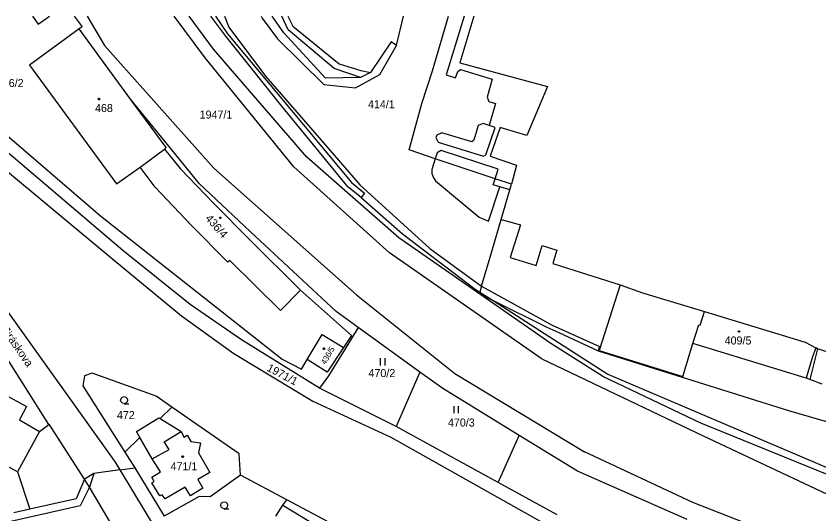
# Model space of a CAD drawing. Extents: x -621797 to -620972, y -1175539 to -1174697.
# Drawn here: x -621483.9 to -621313.4, y -1174804.6 to -1174699 of the extents above; entities that cross this region are included whole.
import ezdxf

# ---------------------------------------------------------------- set-up
doc = ezdxf.new("R2010")
doc.units = 0
for name, color, linetype in [('INZ mimo EON - nadz', 7, 'Continuous'), ('Rozvod plynu EON', 7, 'Continuous'), ('SDEL EON', 7, 'Continuous'), ('SDEL EON - popis', 7, 'Continuous'), ('Silnoproud EON', 7, 'Continuous'), ('Silnoproud EON - popis', 7, 'Continuous')]:
    doc.layers.add(name, color=color, linetype=linetype)

msp = doc.modelspace()

# ---------------------------------------------------------------- linework, layer by layer
at = {"layer": 'Rozvod plynu EON'}
for points in [[(-621466.21, -1174716.4), (-621466.12, -1174716.55), (-621466.21, -1174716.7), (-621466.39, -1174716.7), (-621466.48, -1174716.55), (-621466.39, -1174716.4)], [(-621440.42, -1174741.62), (-621440.33, -1174741.77), (-621440.42, -1174741.92), (-621440.6, -1174741.92), (-621440.69, -1174741.77), (-621440.6, -1174741.62)], [(-621330.31, -1174765.75), (-621330.22, -1174765.9), (-621330.31, -1174766.05), (-621330.49, -1174766.05), (-621330.58, -1174765.9), (-621330.49, -1174765.75)], [(-621418.44, -1174769.38), (-621418.35, -1174769.53), (-621418.44, -1174769.68), (-621418.62, -1174769.68), (-621418.71, -1174769.53), (-621418.62, -1174769.38)], [(-621448.44, -1174792.3), (-621448.35, -1174792.45), (-621448.44, -1174792.6), (-621448.62, -1174792.6), (-621448.71, -1174792.45), (-621448.62, -1174792.3)]]:
    msp.add_lwpolyline(points, close=True, dxfattribs=at)
at = {"layer": 'SDEL EON'}
for p, q in [((-621406.55, -1174771.58), (-621406.55, -1174773.08)), ((-621405.55, -1174773.08), (-621405.55, -1174771.58)), ((-621390.95, -1174781.71), (-621390.95, -1174783.21)), ((-621389.95, -1174783.21), (-621389.95, -1174781.71))]:
    msp.add_line(p, q, dxfattribs=at)
for points in [[(-621460.93, -1174781.19), (-621461.31, -1174781.09), (-621461.58, -1174780.82), (-621461.68, -1174780.45), (-621461.58, -1174780.08), (-621461.31, -1174779.81), (-621460.94, -1174779.71), (-621460.57, -1174779.81), (-621460.3, -1174780.08), (-621460.2, -1174780.46), (-621460.3, -1174780.84), (-621460.57, -1174781.11), (-621460.95, -1174781.21), (-621459.95, -1174781.21)], [(-621439.69, -1174803.5), (-621440.07, -1174803.4), (-621440.34, -1174803.13), (-621440.44, -1174802.76), (-621440.34, -1174802.39), (-621440.07, -1174802.12), (-621439.7, -1174802.02), (-621439.33, -1174802.12), (-621439.06, -1174802.39), (-621438.96, -1174802.77), (-621439.06, -1174803.15), (-621439.33, -1174803.42), (-621439.71, -1174803.52), (-621438.71, -1174803.52)]]:
    msp.add_lwpolyline(points, dxfattribs=at)
at = {"layer": 'SDEL EON - popis'}
for p, q in [((-621468.802, -1174698.96), (-621465.12, -1174705.2)), ((-621443.71, -1174707.79), (-621450.351, -1174698.96)), ((-621442.35, -1174699.28), (-621442.563, -1174698.96)), ((-621439.36, -1174703.2), (-621442.35, -1174699.28)), ((-621441.542, -1174698.96), (-621439, -1174702.7)), ((-621431.858, -1174698.96), (-621431.64, -1174699.42)), ((-621431.64, -1174699.42), (-621428.41, -1174703.82)), ((-621427.05, -1174702.51), (-621429.478, -1174698.96)), ((-621426.13, -1174701.85), (-621427.487, -1174698.96)), ((-621426.21, -1174698.96), (-621425.12, -1174701.13)), ((-621403.08, -1174705.22), (-621401.632, -1174698.96)), ((-621388.71, -1174698.96), (-621392.56, -1174711.42)), ((-621386.669, -1174698.96), (-621389.68, -1174708.86)), ((-621425.12, -1174701.13), (-621415.27, -1174709.1)), ((-621427.46, -1174718.1), (-621439.36, -1174703.2)), ((-621439, -1174702.7), (-621426.74, -1174717.4)), ((-621418.2, -1174712.15), (-621427.05, -1174702.51)), ((-621416.32, -1174710.11), (-621426.13, -1174701.85)), ((-621428.41, -1174703.82), (-621418.55, -1174713.48)), ((-621404.23, -1174704.42), (-621408.6, -1174710.95)), ((-621403.08, -1174705.22), (-621404.23, -1174704.42)), ((-621465.12, -1174705.2), (-621441.9, -1174731.26)), ((-621406.68, -1174711.35), (-621403.08, -1174705.22)), ((-621424.92, -1174730.95), (-621443.71, -1174707.79)), ((-621410.72, -1174712.01), (-621416.32, -1174710.11)), ((-621415.27, -1174709.1), (-621410.66, -1174710.51)), ((-621389.68, -1174708.86), (-621371.05, -1174713.9)), ((-621411.85, -1174714.16), (-621406.68, -1174711.35)), ((-621408.6, -1174710.95), (-621410.72, -1174712.01)), ((-621410.66, -1174710.51), (-621408.6, -1174710.95)), ((-621392.56, -1174711.42), (-621390.58, -1174712.1)), ((-621390.58, -1174712.1), (-621390.09, -1174710.72)), ((-621390.09, -1174710.72), (-621389.51, -1174710.28)), ((-621389.51, -1174710.28), (-621382.83, -1174712.37)), ((-621499.28, -1174712.78), (-621465.93, -1174741.34)), ((-621418.55, -1174713.48), (-621411.85, -1174714.16)), ((-621410.72, -1174712.01), (-621418.2, -1174712.15)), ((-621382.83, -1174712.37), (-621383.89, -1174716.19)), ((-621371.05, -1174713.9), (-621375.46, -1174724.27)), ((-621383.89, -1174716.19), (-621383.52, -1174717.06)), ((-621413.37, -1174735.29), (-621427.46, -1174718.1)), ((-621426.74, -1174717.4), (-621412.65, -1174734.3)), ((-621383.52, -1174717.06), (-621382.09, -1174717.53)), ((-621382.09, -1174717.53), (-621383.46, -1174722.16)), ((-621384.73, -1174721.75), (-621385.77, -1174722.2)), ((-621383.46, -1174722.16), (-621384.73, -1174721.75)), ((-621393.51, -1174723.72), (-621394.56, -1174724.26)), ((-621387.12, -1174725.62), (-621393.51, -1174723.72)), ((-621385.77, -1174722.2), (-621386.72, -1174725.27)), ((-621384.11, -1174728.42), (-621382.16, -1174722.58)), ((-621382.16, -1174722.58), (-621383.46, -1174722.16)), ((-621381.11, -1174722.58), (-621383.19, -1174728.68)), ((-621375.46, -1174724.27), (-621381.11, -1174722.58)), ((-621394.56, -1174724.26), (-621394.76, -1174724.75)), ((-621394.76, -1174724.75), (-621394.24, -1174725.69)), ((-621386.72, -1174725.27), (-621387.12, -1174725.62)), ((-621394.24, -1174725.69), (-621384.65, -1174728.68)), ((-621394.49, -1174727.98), (-621394.9, -1174729.24)), ((-621393.61, -1174727.47), (-621394.49, -1174727.98)), ((-621381.5, -1174731.43), (-621393.61, -1174727.47)), ((-621384.65, -1174728.68), (-621384.11, -1174728.42)), ((-621383.19, -1174728.68), (-621377.63, -1174730.58)), ((-621394.9, -1174729.24), (-621395.63, -1174731.5)), ((-621441.9, -1174731.26), (-621411.59, -1174758.13)), ((-621404.62, -1174749.2), (-621424.92, -1174730.95)), ((-621395.63, -1174731.5), (-621395.61, -1174732.39)), ((-621382.17, -1174733.49), (-621381.5, -1174731.43)), ((-621377.63, -1174730.58), (-621378.72, -1174734.65)), ((-621395.61, -1174732.39), (-621395.29, -1174733.27)), ((-621395.29, -1174733.27), (-621394.85, -1174733.94)), ((-621394.85, -1174733.94), (-621385.58, -1174741.65)), ((-621382.6, -1174734.79), (-621382.17, -1174733.49)), ((-621410.61, -1174737.48), (-621413.37, -1174735.29)), ((-621412.65, -1174734.3), (-621409.93, -1174736.57)), ((-621383.56, -1174742.46), (-621381.16, -1174735.21)), ((-621381.16, -1174735.21), (-621382.6, -1174734.79)), ((-621379.06, -1174735.82), (-621381.16, -1174735.21)), ((-621409.93, -1174736.57), (-621410.61, -1174737.48)), ((-621410.61, -1174737.48), (-621401.84, -1174745.2)), ((-621465.93, -1174741.34), (-621427.37, -1174771.79)), ((-621385.58, -1174741.65), (-621383.56, -1174742.46)), ((-621380.91, -1174742.13), (-621376.81, -1174743.24)), ((-621376.81, -1174743.24), (-621378.96, -1174750.2)), ((-621401.84, -1174745.2), (-621386.41, -1174756.88)), ((-621372.39, -1174771.62), (-621404.62, -1174749.2)), ((-621373.49, -1174751.92), (-621372.17, -1174747.66)), ((-621372.17, -1174747.66), (-621369.05, -1174748.62)), ((-621369.05, -1174748.62), (-621369.93, -1174751.49)), ((-621378.96, -1174750.2), (-621373.49, -1174751.92)), ((-621369.93, -1174751.49), (-621355.64, -1174755.99)), ((-621355.64, -1174755.99), (-621360.06, -1174769.93)), ((-621355.64, -1174755.99), (-621350.85, -1174757.71)), ((-621423.47, -1174757.15), (-621412.66, -1174766.73)), ((-621386.41, -1174756.88), (-621385.42, -1174757.52)), ((-621385.42, -1174757.52), (-621382.57, -1174759.34)), ((-621385.06, -1174756.29), (-621370.06, -1174764.58)), ((-621350.85, -1174757.71), (-621337.7, -1174761.64)), ((-621411.59, -1174758.13), (-621390.7, -1174774.81)), ((-621382.57, -1174759.34), (-621369.69, -1174767.58)), ((-621370.06, -1174764.58), (-621360.01, -1174769.05)), ((-621412.66, -1174766.73), (-621414.35, -1174769.32)), ((-621369.69, -1174767.58), (-621358.21, -1174774.93)), ((-621360.01, -1174769.05), (-621360.28, -1174770.03)), ((-621342.32, -1174775.41), (-621340.2, -1174768.47)), ((-621313.73, -1174769.59), (-621315.34, -1174776.05)), ((-621313.73, -1174769.59), (-621314.1, -1174769.35)), ((-621249.98, -1174789.27), (-621313.73, -1174769.59)), ((-621360.06, -1174769.93), (-621342.32, -1174775.41)), ((-621427.37, -1174771.79), (-621423.25, -1174773.91)), ((-621423.25, -1174773.91), (-621422.11, -1174771.81)), ((-621372.39, -1174771.62), (-621338, -1174788.06)), ((-621390.7, -1174774.81), (-621363.22, -1174791.43)), ((-621358.21, -1174774.93), (-621305.79, -1174797.28)), ((-621315.34, -1174776.05), (-621316.14, -1174775.82)), ((-621312.71, -1174777.06), (-621315.34, -1174776.05)), ((-621453.31, -1174784.34), (-621448.83, -1174787.11)), ((-621478.9, -1174787.1), (-621483.6, -1174795.66)), ((-621454.97, -1174792.88), (-621457.58, -1174788.41)), ((-621452.42, -1174789.29), (-621448.83, -1174787.11)), ((-621448.83, -1174787.11), (-621448.25, -1174788.29)), ((-621448.25, -1174788.29), (-621447.54, -1174787.88)), ((-621447.54, -1174787.88), (-621446.8, -1174789.23)), ((-621338, -1174788.06), (-621307.33, -1174802.47)), ((-621451.38, -1174790.93), (-621452.42, -1174789.29)), ((-621446.8, -1174789.23), (-621444.7, -1174789.5)), ((-621444.7, -1174789.5), (-621445.16, -1174791.62)), ((-621454.97, -1174792.88), (-621451.38, -1174790.93)), ((-621445.16, -1174791.62), (-621442.74, -1174795.78)), ((-621340.16, -1174802.18), (-621363.22, -1174791.43)), ((-621483.6, -1174795.66), (-621487.41, -1174793.6)), ((-621453.23, -1174795.64), (-621454.97, -1174792.88)), ((-621461.85, -1174795.25), (-621402.58, -1174893.11)), ((-621483.6, -1174795.66), (-621480.94, -1174803.61)), ((-621467.38, -1174796.02), (-621468.3, -1174798.95)), ((-621455.09, -1174796.8), (-621453.23, -1174795.64)), ((-621454.55, -1174797.71), (-621455.09, -1174796.8)), ((-621442.74, -1174795.78), (-621445.31, -1174797.31)), ((-621455.04, -1174798.01), (-621454.55, -1174797.71)), ((-621453.37, -1174800.79), (-621455.04, -1174798.01)), ((-621445.31, -1174797.31), (-621444.22, -1174799.14)), ((-621468.3, -1174798.95), (-621470.29, -1174802.9)), ((-621448, -1174798.9), (-621452.25, -1174801.41)), ((-621446.85, -1174800.74), (-621448, -1174798.9)), ((-621444.22, -1174799.14), (-621446.85, -1174800.74)), ((-621452.87, -1174800.52), (-621453.37, -1174800.79)), ((-621452.25, -1174801.41), (-621452.87, -1174800.52)), ((-621470.29, -1174802.9), (-621493.86, -1174808.23)), ((-621427.21, -1174802.78), (-621419.69, -1174807.36)), ((-621323.55, -1174808.67), (-621340.16, -1174802.18))]:
    msp.add_line(p, q, dxfattribs=at)
at = {"layer": 'Silnoproud EON'}
for p, q in [((-621480.414, -1174698.96), (-621479.19, -1174700.68)), ((-621479.19, -1174700.68), (-621476.788, -1174698.96)), ((-621471.523, -1174698.96), (-621469.88, -1174701.25)), ((-621441.97, -1174705.95), (-621447.1, -1174698.96)), ((-621439.637, -1174698.96), (-621438.72, -1174701.33)), ((-621395.48, -1174710.6), (-621392.081, -1174698.96)), ((-621469.88, -1174701.25), (-621470.51, -1174701.7)), ((-621438.72, -1174701.33), (-621430.9, -1174711.72)), ((-621470.51, -1174701.7), (-621481.06, -1174709.36)), ((-621459.57, -1174716.57), (-621470.51, -1174701.7)), ((-621422.13, -1174728.91), (-621441.97, -1174705.95)), ((-621513.67, -1174708.79), (-621462.91, -1174750.9)), ((-621481.06, -1174709.36), (-621462.56, -1174734.54)), ((-621430.9, -1174711.72), (-621419.52, -1174724.79)), ((-621397.72, -1174717.48), (-621395.48, -1174710.6)), ((-621461.21, -1174748.72), (-621500.92, -1174714.95)), ((-621452.64, -1174725.1), (-621459.57, -1174716.57)), ((-621451.99, -1174726.87), (-621459.57, -1174716.57)), ((-621400.44, -1174727.38), (-621397.72, -1174717.48)), ((-621444.97, -1174734.55), (-621452.64, -1174725.1)), ((-621419.52, -1174724.79), (-621410.9, -1174734.74)), ((-621452.39, -1174727.17), (-621451.99, -1174726.87)), ((-621457.57, -1174731), (-621452.39, -1174727.17)), ((-621452.39, -1174727.17), (-621449.03, -1174731.31)), ((-621394.9, -1174729.24), (-621400.44, -1174727.38)), ((-621402.61, -1174746.04), (-621422.13, -1174728.91)), ((-621382.17, -1174733.49), (-621394.9, -1174729.24)), ((-621462.56, -1174734.54), (-621457.57, -1174731)), ((-621454.34, -1174735.3), (-621457.57, -1174731)), ((-621449.03, -1174731.31), (-621441.96, -1174738.68)), ((-621378.72, -1174734.65), (-621382.17, -1174733.49)), ((-621446.67, -1174743.39), (-621454.34, -1174735.3)), ((-621434.16, -1174744.65), (-621444.97, -1174734.55)), ((-621410.9, -1174734.74), (-621396, -1174748.28)), ((-621379.06, -1174735.82), (-621378.72, -1174734.65)), ((-621380.91, -1174742.13), (-621379.06, -1174735.82)), ((-621441.96, -1174738.68), (-621434.16, -1174746.51)), ((-621383.24, -1174750.1), (-621380.91, -1174742.13)), ((-621438.9, -1174751.16), (-621446.67, -1174743.39)), ((-621415.93, -1174761.66), (-621434.16, -1174744.65)), ((-621434.16, -1174746.51), (-621423.47, -1174757.15)), ((-621370.32, -1174768.47), (-621402.61, -1174746.04)), ((-621446.92, -1174760.16), (-621461.21, -1174748.72)), ((-621396, -1174748.28), (-621385.06, -1174756.29)), ((-621494.1, -1174749.94), (-621462.84, -1174793.62)), ((-621462.91, -1174750.9), (-621448.78, -1174762.54)), ((-621438.5, -1174750.8), (-621438.9, -1174751.16)), ((-621427.77, -1174761.47), (-621438.5, -1174750.8)), ((-621385.06, -1174756.29), (-621383.24, -1174750.1)), ((-621476.96, -1174785.62), (-621498.01, -1174752.31)), ((-621423.47, -1174757.15), (-621427.77, -1174761.47)), ((-621385.42, -1174757.52), (-621385.52, -1174757.88)), ((-621385.06, -1174756.29), (-621385.42, -1174757.52)), ((-621385.52, -1174757.88), (-621382.57, -1174759.34)), ((-621382.57, -1174759.34), (-621371.17, -1174764.97)), ((-621436.01, -1174767.68), (-621446.92, -1174760.16)), ((-621448.78, -1174762.54), (-621437.66, -1174770.55)), ((-621411.24, -1174765.05), (-621415.93, -1174761.66)), ((-621338.66, -1174764.58), (-621337.7, -1174761.64)), ((-621337.7, -1174761.64), (-621316.34, -1174768.15)), ((-621340.2, -1174768.47), (-621338.9, -1174764.51)), ((-621338.9, -1174764.51), (-621338.66, -1174764.58)), ((-621411.24, -1174765.05), (-621412.67, -1174767.36)), ((-621398.13, -1174774.52), (-621411.24, -1174765.05)), ((-621371.17, -1174764.97), (-621368.65, -1174766.14)), ((-621368.65, -1174766.14), (-621360.28, -1174770.03)), ((-621419.48, -1174777.93), (-621436.01, -1174767.68)), ((-621422.11, -1174771.81), (-621418.91, -1174766.5)), ((-621418.91, -1174766.5), (-621414.35, -1174769.32)), ((-621412.67, -1174767.36), (-621417.58, -1174775.27)), ((-621414.35, -1174769.32), (-621417.86, -1174774.53)), ((-621359.15, -1174775.51), (-621370.32, -1174768.47)), ((-621316.14, -1174775.82), (-621340.2, -1174768.47)), ((-621316.34, -1174768.15), (-621314.1, -1174769.35)), ((-621314.1, -1174769.35), (-621314.84, -1174771.47)), ((-621437.66, -1174770.55), (-621420.9, -1174780.7)), ((-621360.28, -1174770.03), (-621319.9, -1174782.64)), ((-621314.84, -1174771.47), (-621316.14, -1174775.82)), ((-621417.86, -1174774.53), (-621422.11, -1174771.81)), ((-621467.76, -1174774.7), (-621469.32, -1174775.31)), ((-621454.16, -1174779.63), (-621467.76, -1174774.7)), ((-621398.13, -1174774.52), (-621403.16, -1174786.07)), ((-621393.29, -1174778.01), (-621398.13, -1174774.52)), ((-621469.32, -1174775.31), (-621469.68, -1174777.45)), ((-621417.58, -1174775.27), (-621419.48, -1174777.93)), ((-621338.51, -1174785.31), (-621359.15, -1174775.51)), ((-621469.68, -1174777.45), (-621460.8, -1174791.48)), ((-621403.16, -1174786.07), (-621419.48, -1174777.93)), ((-621377.08, -1174787.93), (-621393.29, -1174778.01)), ((-621486.57, -1174779.12), (-621481.69, -1174781.84)), ((-621450.8, -1174781.95), (-621454.16, -1174779.63)), ((-621420.9, -1174780.7), (-621404.3, -1174788.29)), ((-621481.69, -1174781.84), (-621483.14, -1174784.65)), ((-621453.31, -1174784.34), (-621450.8, -1174781.95)), ((-621436.53, -1174791.83), (-621450.8, -1174781.95)), ((-621319.9, -1174782.64), (-621244.1, -1174804.58)), ((-621483.14, -1174784.65), (-621478.9, -1174787.1)), ((-621458.34, -1174787.12), (-621453.58, -1174784.18)), ((-621453.58, -1174784.18), (-621453.31, -1174784.34)), ((-621478.9, -1174787.1), (-621476.96, -1174785.62)), ((-621476.88, -1174785.56), (-621476.96, -1174785.62)), ((-621469.33, -1174797.24), (-621476.88, -1174785.56)), ((-621381.53, -1174797.95), (-621403.16, -1174786.07)), ((-621307.08, -1174798.09), (-621338.51, -1174785.31)), ((-621460.8, -1174791.48), (-621457.58, -1174788.41)), ((-621457.58, -1174788.41), (-621458.34, -1174787.12)), ((-621404.3, -1174788.29), (-621370.31, -1174807.44)), ((-621381.53, -1174797.95), (-621377.08, -1174787.93)), ((-621364.7, -1174795.51), (-621377.08, -1174787.93)), ((-621460.8, -1174791.48), (-621458.69, -1174794.8)), ((-621436.22, -1174796.37), (-621436.53, -1174791.83)), ((-621462.84, -1174793.62), (-621461.85, -1174795.25)), ((-621461.85, -1174795.25), (-621467.38, -1174796.02)), ((-621461.85, -1174795.25), (-621458.69, -1174794.8)), ((-621458.69, -1174794.8), (-621452.45, -1174805.11)), ((-621467.38, -1174796.02), (-621469.33, -1174797.24)), ((-621436.22, -1174796.37), (-621442.66, -1174800.98)), ((-621426.41, -1174801.58), (-621436.22, -1174796.37)), ((-621341.37, -1174805.79), (-621364.7, -1174795.51)), ((-621469.33, -1174797.24), (-621471.15, -1174801.39)), ((-621468.3, -1174798.95), (-621469.33, -1174797.24)), ((-621369.02, -1174804.81), (-621381.53, -1174797.95)), ((-621461.99, -1174809.51), (-621468.3, -1174798.95)), ((-621471.15, -1174801.39), (-621480.94, -1174803.61)), ((-621445.02, -1174800.92), (-621452.45, -1174805.11)), ((-621442.66, -1174800.98), (-621445.02, -1174800.92)), ((-621427.21, -1174802.78), (-621426.41, -1174801.58)), ((-621412.27, -1174809.1), (-621426.41, -1174801.58)), ((-621480.94, -1174803.61), (-621484.34, -1174804.38)), ((-621428.73, -1174805.08), (-621427.21, -1174802.78))]:
    msp.add_line(p, q, dxfattribs=at)

# ---------------------------------------------------------------- texts
at = {"layer": 'INZ mimo EON - nadz'}
msp.add_text('1947/1', height=1.7, dxfattribs=at).set_placement((-621444.917, -1174720.71))
msp.add_text('Jiráskova', height=1.7, rotation=304.52707, dxfattribs=at).set_placement((-621486.963, -1174765.659))
at = {"layer": 'Silnoproud EON - popis'}
for s, p in [('436/2', (-621487.973, -1174714.02)), ('414/1', (-621409.173, -1174718.53)), ('468', (-621467.123, -1174719.33)), ('409/5', (-621333.443, -1174768.65)), ('470/2', (-621409.063, -1174775.56)), ('472', (-621462.473, -1174784.48)), ('470/3', (-621392.193, -1174786.06)), ('471/1', (-621451.087, -1174795.34))]:
    msp.add_text(s, height=1.7, dxfattribs=at).set_placement(p)
for s, height, rotation, p in [('436/4', 1.7, 311.40256, (-621443.823, -1174741.968)), ('436/5', 1.2, 59.41572, (-621418.205, -1174773.016)), ('1971/1', 1.7, 332.08634, (-621430.793, -1174774.134))]:
    msp.add_text(s, height=height, rotation=rotation, dxfattribs=at).set_placement(p)

doc.saveas('drawing.dxf')
